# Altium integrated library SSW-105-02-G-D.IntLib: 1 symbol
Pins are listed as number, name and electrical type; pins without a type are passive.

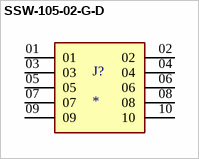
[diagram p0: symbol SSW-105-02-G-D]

## SSW-105-02-G-D
designator J?
MP: SSW-105-02-G-D; MF: Samtec Inc.
footprint SAMTEC_SSW-105-02-G-D
pins: 01, 02, 03, 04, 05, 06, 07, 08, 09, 10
